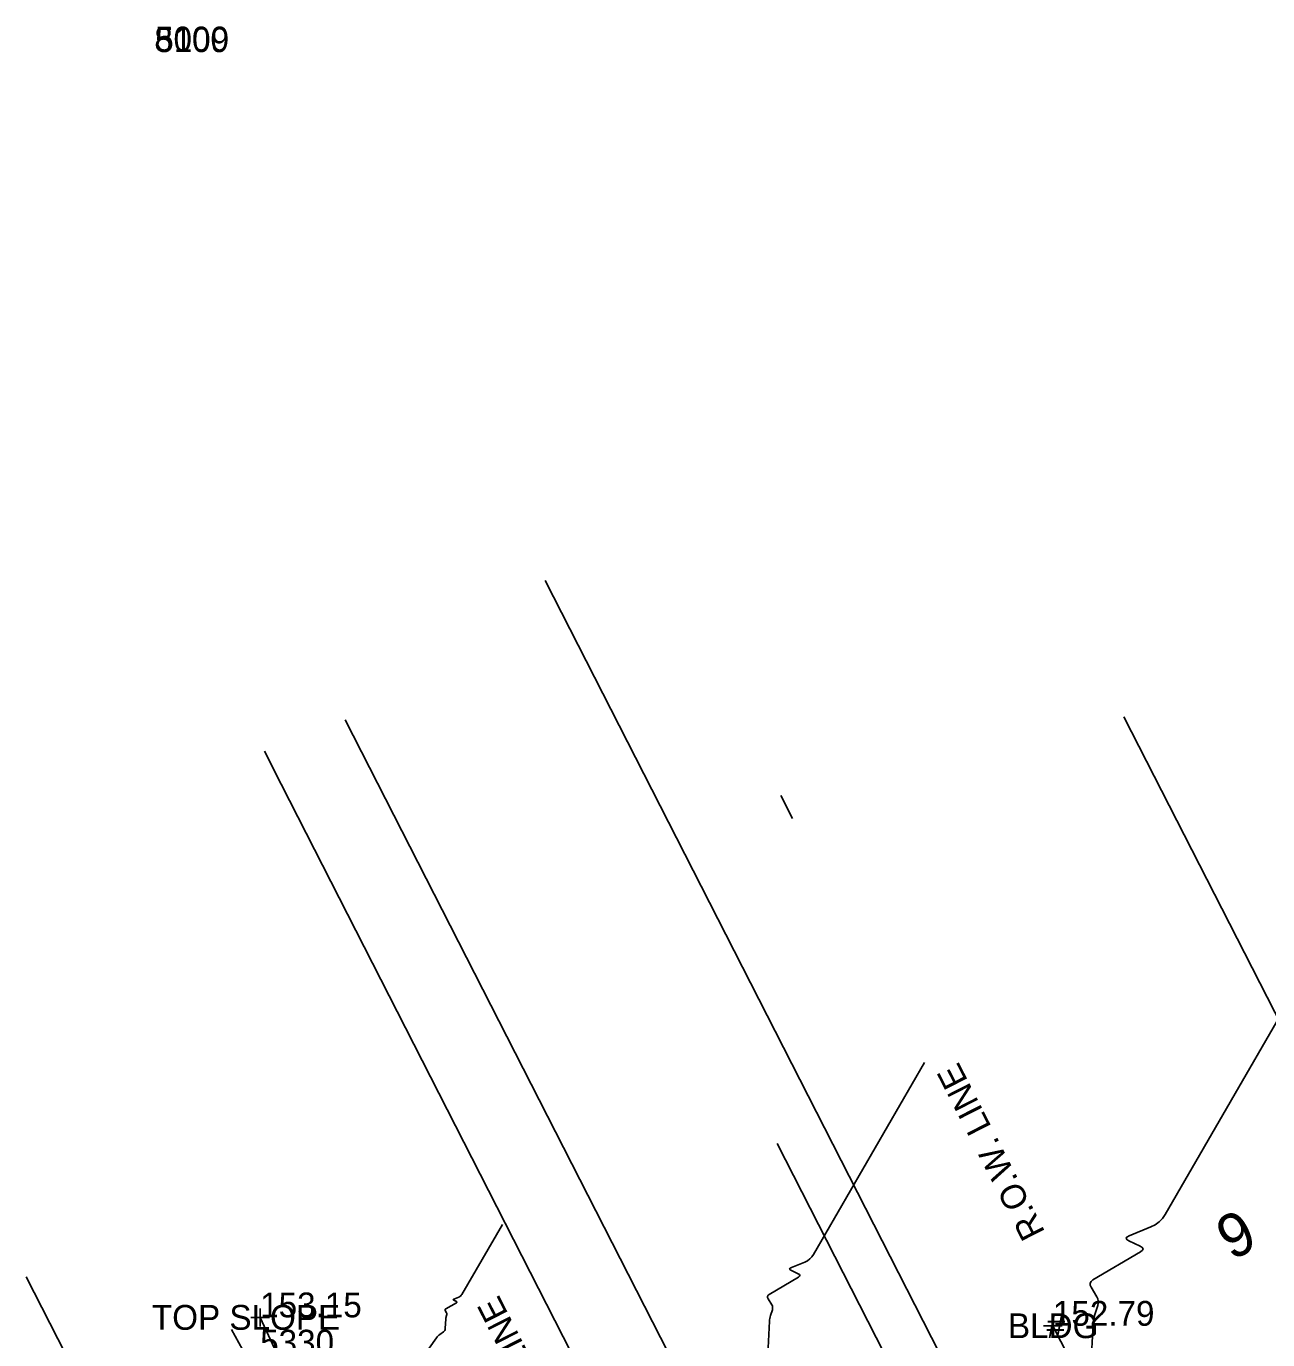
# Model space of a CAD drawing. Extents: x 13482495 to 13483389, y 311646 to 312209.
# Drawn here: x 13482806.9 to 13482966.8, y 311979.8 to 312149.1 of the extents above; entities that cross this region are included whole.
import ezdxf

# ---------------------------------------------------------------- set-up
doc = ezdxf.new("R2010")
doc.units = 0
for name, color, linetype in [('V-BLDG-OTLN', 7, 'Continuous'), ('V-PROP-IDEN', 7, 'Continuous'), ('V-PROP-LINE', 7, 'Continuous'), ('V-PROP-RWAY', 7, 'Continuous'), ('V-PROP-RWAY-IDEN', 7, 'Continuous'), ('V-SITE-SPOT', 7, 'Continuous'), ('V-STRM-MAIN', 7, 'Continuous'), ('V-SURV-PNTS', 7, 'Continuous'), ('V-TOPO-DRAN-SPOT', 7, 'Continuous'), ('V-TOPO-DRAN-TOP', 7, 'Continuous'), ('V-TOPO-LINE-IDEN', 7, 'Continuous'), ('V-TOPO-MAJR', 7, 'Continuous'), ('V-TOPO-MINR', 7, 'Continuous'), ('V-UTIL-UNDR', 7, 'Continuous')]:
    doc.layers.add(name, color=color, linetype=linetype)

msp = doc.modelspace()

# ---------------------------------------------------------------- linework, layer by layer
at = {"layer": 'V-BLDG-OTLN'}
msp.add_lwpolyline([(13482939.17, 311981.6), (13482950.47, 311959.45), (13482969.24, 311968.91)], dxfattribs=at)
at = {"layer": 'V-PROP-LINE'}
for p, q in [((13482948.32, 312060.05), (13482992.56, 311973.37)), ((13482851.12, 311901.27), (13482806.92, 311987.91))]:
    msp.add_line(p, q, dxfattribs=at)
at = {"layer": 'V-PROP-RWAY'}
msp.add_line((13482904.12, 312049.92), (13482905.63, 312046.96), dxfattribs=at)
at = {"layer": 'V-SITE-SPOT'}
for p, q in [((13482939.17, 311982.76), (13482939.17, 311980.44)), ((13482937.97, 311981.6), (13482940.37, 311981.6))]:
    msp.add_line(p, q, dxfattribs=at)
at = {"layer": 'V-STRM-MAIN'}
msp.add_line((13482903.65, 312005.08), (13482965.15, 311884.57), dxfattribs=at)
at = {"layer": 'V-TOPO-DRAN-SPOT'}
for p, q in [((13482837.05, 311983.84), (13482837.05, 311981.52)), ((13482835.85, 311982.68), (13482838.25, 311982.68))]:
    msp.add_line(p, q, dxfattribs=at)
at = {"layer": 'V-TOPO-DRAN-TOP'}
msp.add_lwpolyline([(13482870.81, 311913.54), (13482867.94, 311920.87), (13482860.93, 311936.11), (13482846.94, 311961.31), (13482837.05, 311982.68)], dxfattribs=at)
at = {"layer": 'V-TOPO-MAJR'}
msp.add_lwpolyline([(13482922.64, 312015.53), (13482908.33, 311990.79), (13482908.11, 311990.47), (13482907.85, 311990.21), (13482907.55, 311989.98), (13482907.21, 311989.81), (13482905.49, 311989.1), (13482905.32, 311989.01), (13482905.26, 311988.91), (13482905.31, 311988.81), (13482905.48, 311988.71), (13482906.36, 311988.3), (13482906.53, 311988.19), (13482906.59, 311988.08), (13482906.54, 311987.97), (13482906.38, 311987.85), (13482902.64, 311985.63), (13482902.49, 311985.52), (13482902.42, 311985.38), (13482902.42, 311985.23), (13482902.49, 311985.06), (13482902.95, 311984.31), (13482903.03, 311984.15), (13482903.07, 311983.98), (13482903.07, 311983.81), (13482903.03, 311983.63), (13482902.8, 311982.91), (13482902.74, 311982.73), (13482902.7, 311982.55), (13482902.68, 311982.37), (13482902.66, 311982.18), (13482902.49, 311978.75)], dxfattribs=at)
at = {"layer": 'V-TOPO-MINR'}
for points in [[(13482977.03, 312036.4), (13482953.62, 311995.94), (13482953.27, 311995.42), (13482952.85, 311994.98), (13482952.36, 311994.62), (13482951.8, 311994.34), (13482948.98, 311993.18), (13482948.7, 311993.02), (13482948.61, 311992.87), (13482948.7, 311992.7), (13482948.97, 311992.54), (13482950.41, 311991.87), (13482950.68, 311991.7), (13482950.78, 311991.52), (13482950.7, 311991.33), (13482950.45, 311991.13), (13482944.31, 311987.51), (13482944.08, 311987.32), (13482943.96, 311987.1), (13482943.96, 311986.85), (13482944.08, 311986.57), (13482944.82, 311985.34), (13482944.95, 311985.08), (13482945.02, 311984.8), (13482945.02, 311984.52), (13482944.96, 311984.23), (13482944.58, 311983.06), (13482944.49, 311982.76), (13482944.43, 311982.47), (13482944.38, 311982.16), (13482944.36, 311981.86), (13482944.07, 311976.25)], [(13482857.15, 311976.33), (13482859.78, 311980.06), (13482859.87, 311980.18), (13482859.96, 311980.28), (13482860.07, 311980.38), (13482860.18, 311980.46), (13482860.65, 311980.8), (13482860.76, 311980.89), (13482860.83, 311980.99), (13482860.88, 311981.11), (13482860.9, 311981.25), (13482860.97, 311982.5), (13482860.97, 311982.57), (13482860.98, 311982.64), (13482861, 311982.7), (13482861.02, 311982.77), (13482861.1, 311983.03), (13482861.11, 311983.09), (13482861.11, 311983.16), (13482861.1, 311983.22), (13482861.07, 311983.28), (13482860.9, 311983.55), (13482860.88, 311983.61), (13482860.88, 311983.67), (13482860.9, 311983.72), (13482860.96, 311983.76), (13482862.32, 311984.57), (13482862.38, 311984.61), (13482862.4, 311984.65), (13482862.38, 311984.69), (13482862.32, 311984.73), (13482861.99, 311984.88), (13482861.93, 311984.92), (13482861.91, 311984.95), (13482861.94, 311984.99), (13482862, 311985.02), (13482862.62, 311985.28), (13482862.75, 311985.35), (13482862.86, 311985.43), (13482862.95, 311985.52), (13482863.03, 311985.64), (13482868.25, 311994.66)], [(13482833.35, 311981.13), (13482834.79, 311978.54)]]:
    msp.add_lwpolyline(points, dxfattribs=at)
at = {"layer": 'V-UTIL-UNDR'}
for p, q in [((13483035.2, 311761.22), (13482873.76, 312077.63)), ((13483006.32, 311749.37), (13482848.01, 312059.67)), ((13482839.75, 312051.39), (13482837.59, 312055.63)), ((13482993.67, 311749.72), (13482839.75, 312051.39))]:
    msp.add_line(p, q, dxfattribs=at)

# ---------------------------------------------------------------- texts
at = {"layer": 'V-PROP-IDEN'}
msp.add_text('9', height=5.6, rotation=27.0313, dxfattribs=at).set_placement((13482962.16, 311989.93))
at = {"layer": 'V-PROP-RWAY-IDEN'}
for p in [(13482938.21, 311993.67), (13482878.99, 311963.64)]:
    msp.add_text('R.O.W. LINE', height=3.2, rotation=117.0313, dxfattribs=at).set_placement(p)
at = {"layer": 'V-SITE-SPOT'}
msp.add_text('152.79', height=3.2, dxfattribs=at).set_placement((13482939.17, 311981.6))
at = {"layer": 'V-SURV-PNTS'}
for s, p in [('8', (13482823.41, 312145.78)), ('8', (13482823.41, 312145.78)), ('5000', (13482823.5, 312145.81)), ('5109', (13482823.53, 312145.73)), ('5330', (13482837.05, 311977.88))]:
    msp.add_text(s, height=3.2, dxfattribs=at).set_placement(p)
at = {"layer": 'V-TOPO-DRAN-SPOT'}
msp.add_text('153.15', height=3.2, dxfattribs=at).set_placement((13482837.05, 311982.68))
at = {"layer": 'V-TOPO-LINE-IDEN'}
for s, p in [('TOP SLOPE', (13482823.1, 311981.08)), ('BLDG', (13482933.38, 311980)), ('#', (13482938.36, 311980))]:
    msp.add_text(s, height=3.2, dxfattribs=at).set_placement(p)

doc.saveas('drawing.dxf')
